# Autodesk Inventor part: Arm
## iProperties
Shininess: 20.0
Length Units: 11269
Angle Units: 11279
Time Units: 11290
Mass Units: 11283
Length Display Precision: 3
Angle Display Precision: 2
Created: 2002-01
Part Number: Arm
Document SubType Name: Modeling
Designer: ***
Density: 0.0
Volumn: 0.0
Area: 0.0
PropertySet Name: Model Information
Control State: 0
Master: False
Checked Out: False
Author: ***
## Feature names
1. Extrusion1
2. Extrusion2
